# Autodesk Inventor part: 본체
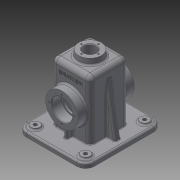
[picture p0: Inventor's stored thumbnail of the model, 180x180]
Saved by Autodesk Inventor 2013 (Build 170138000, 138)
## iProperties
Created: 2016-01
Part Number: 본체
Material: 일반
Document SubType Name: Modeling
Designer: User
Density: 1 g/cm^3
Author: User
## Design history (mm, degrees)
sketch "스케치1"
  geometry: L1 (-65, 57.5)-(65, 57.5); L2 (65, 57.5)-(65, -57.5); L3 (65, -57.5)-(-65, -57.5); L4 (-65, -57.5)-(-65, 57.5); L5 (-65, 57.5)-(65, -57.5); L6 (65, 57.5)-(-65, -57.5); 1 further point
  constraints: 12 end point, 2 midpoint, 2 parallel, 1 horizontal, 1 perpendicular
  dimensions: "d0" = 130 distance of L1.start L1.end; "d3" = 115 distance of L1.end L2.end
extrude "돌출1" new body sketch "스케치1" distance "d4" = 8; taper "d5" = 0 deg
sketch "스케치2"
  geometry: L1 (-60, 52.5)-(60, 52.5); L2 (60, 52.5)-(60, -52.5); L3 (60, -52.5)-(-60, -52.5); L4 (-60, -52.5)-(-60, 52.5); L5 (-60, 52.5)-(60, -52.5); L6 (60, 52.5)-(-60, -52.5); 1 further point
  constraints: 12 end point, 2 midpoint, 2 parallel, 1 horizontal, 1 perpendicular
  dimensions: "d6" = 120 distance of L1.start L1.end; "d8" = 105 distance of L1.end L2.end
extrude "돌출2" join sketch "스케치2" distance "d10" = 2; taper "d11" = 0 deg
sketch "스케치3"
  geometry: L1 (-32.5, 32.5)-(32.5, 32.5); L2 (32.5, 32.5)-(32.5, -32.5); L3 (32.5, -32.5)-(-32.5, -32.5); L4 (-32.5, -32.5)-(-32.5, 32.5); L5 (-32.5, 32.5)-(32.5, -32.5); L6 (32.5, 32.5)-(-32.5, -32.5); 1 further point
  constraints: 12 end point, 2 midpoint, 2 parallel, 1 horizontal, 1 perpendicular
  dimensions: "d12" = 65 distance of L1.start L1.end; "d14" = 65 distance of L1.end L2.end
extrude "돌출3" join sketch "스케치3" distance "d15" = 100; taper "d16" = 0 deg
sketch "스케치4"
  geometry: C1 r 20 at (0, 0); C2 r 10.5 at (0, 0); 1 further point
  constraints: 2 centre point, 2 coincident
  dimensions: "d17" = 40 diameter of C1; "d19" = 21 diameter of C2
extrude "돌출4" join sketch "스케치4" distance "d20" = 10; taper "d21" = 0 deg
sketch "스케치5"
  geometry: L1 (-27.5, 27.5)-(27.5, 27.5); L2 (27.5, 27.5)-(27.5, -27.5); L3 (27.5, -27.5)-(-27.5, -27.5); L4 (-27.5, -27.5)-(-27.5, 27.5); L5 (-27.5, 27.5)-(27.5, -27.5); L6 (27.5, 27.5)-(-27.5, -27.5); 1 further point
  constraints: 12 end point, 2 midpoint, 2 parallel, 1 horizontal, 1 perpendicular
  dimensions: "d22" = 55 distance of L1.start L1.end; "d24" = 55 distance of L1.end L2.end
extrude "돌출5" cut sketch "스케치5" distance "d25" = 105; taper "d26" = 0 deg
extrude "돌출6" cut sketch "스케치4" distance "d27" = 105; taper "d28" = 0 deg
sketch "스케치6"
  geometry: L1 (0, 0)-(-100, 0) reference; L2 (10, 85)-(10, -20) reference; C1 r 27.5 at (-45, 32.5); C2 r 17.5 at (-45, 32.5); 1 further point
  constraints: 2 centre point, 1 coincident
  dimensions: "d29" = 55 diameter of C1; "d30" = 35 diameter of C2; "d31" = 55 distance from line of C2.centre L2; "d32" = 32.5 distance from line of C1.centre L1
extrude "돌출7" join sketch "스케치6" distance "d33" = 15; taper "d34" = 0 deg
extrude "돌출8" cut sketch "스케치6" distance "d35" = 2; taper "d36" = 0 deg
sketch "스케치7"
  geometry: L1 (0, 0)-(100, 0) reference; L2 (-10, -20)-(-10, 85) reference; C1 r 27.5 at (45, 32.5); C2 r 17.5 at (45, 32.5); 1 further point
  constraints: 2 centre point, 1 coincident
  dimensions: "d37" = 55 diameter of C1; "d38" = 35 diameter of C2; "d39" = 55 distance from line of L2 C2.centre; "d40" = 32.5 distance from line of L1 C1.centre
extrude "돌출9" join sketch "스케치7" distance "d41" = 15; taper "d42" = 0 deg
extrude "돌출10" cut sketch "스케치7" distance "d43" = 2; taper "d44" = 0 deg
hole "구멍1" diameter "d47" = 30; stored, may be unused: countersink angle "d51" = 90 deg, drill point angle "d53" = 118 deg; dims "d45" = 10, "d46" = 10, "d48" = 6, "d49" = 4, "d50" = 2, "d52" = 8
sketch "스케치8"
  geometry: L1 (65, 57.5)-(-65, 57.5) reference; L2 (-65, 57.5)-(-65, -57.5) reference; L3 (-65, -57.5)-(65, -57.5) reference; L4 (65, -57.5)-(65, 57.5) reference; C1 r 7.5 at (-50, 42.5); C2 r 7.5 at (50, 42.5); C3 r 7.5 at (50, -42.5); C4 r 7.5 at (-50, -42.5); 1 further point
  constraints: 4 centre point
  dimensions: "d54" = 15 diameter of C1; "d55" = 15 diameter of C2; "d56" = 15 diameter of C3; "d57" = 15 diameter of C4; "d58" = 15 distance from line of L2 C1.centre; "d59" = 100 distance of C2.centre C1.centre; "d60" = 15 distance from line of L1 C2.centre; "d61" = 15 distance from line of C1.centre L1; "d62" = 15 distance from line of L2 C4.centre; "d63" = 15 distance from line of L3 C4.centre; "d64" = 15 distance from line of L4 C3.centre; "d65" = 15 distance from line of L3 C3.centre
extrude "돌출11" join sketch "스케치8" distance "d66" = 3; taper "d67" = 0 deg
hole "구멍2" diameter "d70" = 6; stored, may be unused: countersink angle "d74" = 90 deg, drill point angle "d76" = 118 deg; dims "d68" = 10, "d69" = 10, "d71" = 6, "d72" = 4, "d73" = 2, "d75" = 8
hole "구멍3" diameter "d79" = 6; stored, may be unused: countersink angle "d83" = 90 deg, drill point angle "d85" = 118 deg; dims "d77" = 10, "d78" = 10, "d80" = 6, "d81" = 4, "d82" = 2, "d84" = 8
hole "구멍4" diameter "d88" = 6; stored, may be unused: countersink angle "d92" = 90 deg, drill point angle "d94" = 118 deg; dims "d86" = 10, "d87" = 10, "d89" = 6, "d90" = 4, "d91" = 2, "d93" = 8
hole "구멍5" diameter "d97" = 6; stored, may be unused: countersink angle "d101" = 90 deg, drill point angle "d103" = 118 deg; dims "d95" = 10, "d96" = 10, "d98" = 6, "d99" = 4, "d100" = 2, "d102" = 8
node "작업 평면1"
sketch "스케치9"
  geometry: L1 (0, -17.5)-(0, -2.5) reference; L2 (0, 90)-(0, -25) reference; L3 (0, 0)-(-100, 0) reference; L4 (0, 65)-(-100, 65) reference; L5 (-85.069, 0)-(0, -15); L6 (-85.069, 65)-(0, 80); L7 (8, -25)-(0, -25) reference; L8 (8, 90)-(0, 90) reference; 1 further point
  constraints: 4 end point, 4 point on line
  dimensions: "d104" = 10 deg angle of L5 L7; "d105" = 10 deg angle of L8 L6; "d106" = 10 distance from line of L7 L5.end; "d107" = 10 distance from line of L8 L6.end
extrude "돌출12" join sketch "스케치9" stored distance "d108" = 10; taper "d109" = 0 deg
sketch "스케치11"
  geometry: L1 (10, 60)-(10, -5) reference; L2 (27.664, 30.5)-(10, 30.5); L3 (27.664, 24.5)-(10, 24.5); L4 (10, 30.5)-(10, 24.5); C1 r 15 at (55, 27.5) reference; A1 r 27.5 centre (55, 27.5) between (27.664, 30.5) and (27.664, 24.5) reference; 2 further points
  constraints: 6 end point, 3 perpendicular, 2 point on circle, 2 point on line, 1 horizontal alignment, 1 midpoint
  dimensions: "d111" = 6 distance between parallel lines of L3 L2
extrude "돌출13" join sketch "스케치11" distance "d112" = 15; taper "d113" = 0 deg
sketch "스케치12"
  geometry: L1 (-10, -5)-(-10, 60) reference; L2 (-10, 24.5)-(-27.664, 24.5); L3 (-10, 30.5)-(-27.664, 30.5); L4 (-10, 30.5)-(-10, 24.5); C1 r 15 at (-55, 27.5) reference; A1 r 27.5 centre (-55, 27.5) between (-27.664, 24.5) and (-27.664, 30.5) reference; 2 further points
  constraints: 6 end point, 2 point on circle, 2 point on line, 1 collinear, 1 horizontal alignment, 1 midpoint, 1 parallel, 1 perpendicular
  dimensions: "d114" = 6 distance between parallel lines of L3 L2
extrude "돌출14" join sketch "스케치12" distance "d116" = 15; taper "d117" = 0 deg
fillet "모깎기1" dims "d118" = 15
sketch "스케치13"
  geometry: L1 (100, 0)-(0, 0) reference; L2 (-10, 52.5)-(-10, 12.5) reference; 2 further points
  constraints: 1 other
  dimensions: "d119" = 32.5 distance from line of point (16, 32.5) L1; "d120" = 26 distance from line of point (16, 32.5) L2
feature "엠보싱1" sketch "스케치13" dims "d121" = 0.5, "d122" = 0
fillet "모깎기2" dims "d123" = 8
fillet "모깎기3" dims "d124" = 10
fillet "모깎기4" dims "d125" = 10
fillet "모깎기5" dims "d126" = 10
fillet "모깎기6" dims "d127" = 3
sketch "스케치14" dims "d128" = 42
  geometry: C1 r 17.5 at (0, 0) reference; C2 r 27.5 at (0, 0) reference; 3 further points
  constraints: 2 horizontal alignment, 1 coincident, 2 other
hole "구멍6" sketch "스케치14" at (21, 0) diameter "d129" = 3.242; stored, may be unused: countersink angle "d133" = 90 deg, drill point angle "d135" = 118 deg; dims "d130" = 8, "d131" = 4, "d132" = 2, "d134" = 10
sketch "스케치15" dims "d139" = 42
  geometry: C1 r 17.5 at (0, 0) reference; C2 r 27.5 at (0, 0) reference; 3 further points
  constraints: 2 horizontal alignment, 1 coincident, 2 other
hole "구멍7" sketch "스케치15" at (-21, 0) diameter "d140" = 3.242; stored, may be unused: countersink angle "d144" = 90 deg, drill point angle "d146" = 118 deg; dims "d141" = 8, "d142" = 4, "d143" = 2, "d145" = 10
sketch "스케치16" dims "d150" = 29
  geometry: C1 r 10.5 at (0, 0) reference; C2 r 20 at (0, 0) reference; 2 further points
  constraints: 2 vertical alignment, 1 coincident, 2 other
hole "구멍8" sketch "스케치16" at (0, 14.5) diameter "d151" = 2.459; stored, may be unused: countersink angle "d155" = 90 deg, drill point angle "d157" = 118 deg; dims "d152" = 7, "d153" = 4, "d154" = 2, "d156" = 9
fillet "모깎기7" dims "d161" = 0.3
chamfer "모따기1" distance "d162" = 1; stored, may be unused: second distance "d163" = 2, angle "d164" = 45 deg
fillet "모깎기8" dims "d165" = 3
fillet "모깎기10" dims "d167" = 8
fillet "모깎기11" dims "d168" = 3
fillet "모깎기12" dims "d169" = 3
fillet "모깎기13" dims "d170" = 3
fillet "모깎기14" dims "d171" = 3
fillet "모깎기15" dims "d172" = 3
fillet "모깎기16" dims "d173" = 3
fillet "모깎기17" dims "d174" = 1
feature "면 기울기1" dims angle "d175" = 5 deg
fillet "모깎기18" dims "d176" = 3
node "솔리드1"
pattern_circular "원형 패턴1" dims angle "d137" = 360 deg
pattern_circular "원형 패턴2" dims angle "d148" = 360 deg
pattern_circular "원형 패턴3" dims angle "d159" = 360 deg
